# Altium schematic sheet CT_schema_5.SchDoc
size 208 x 258 mm
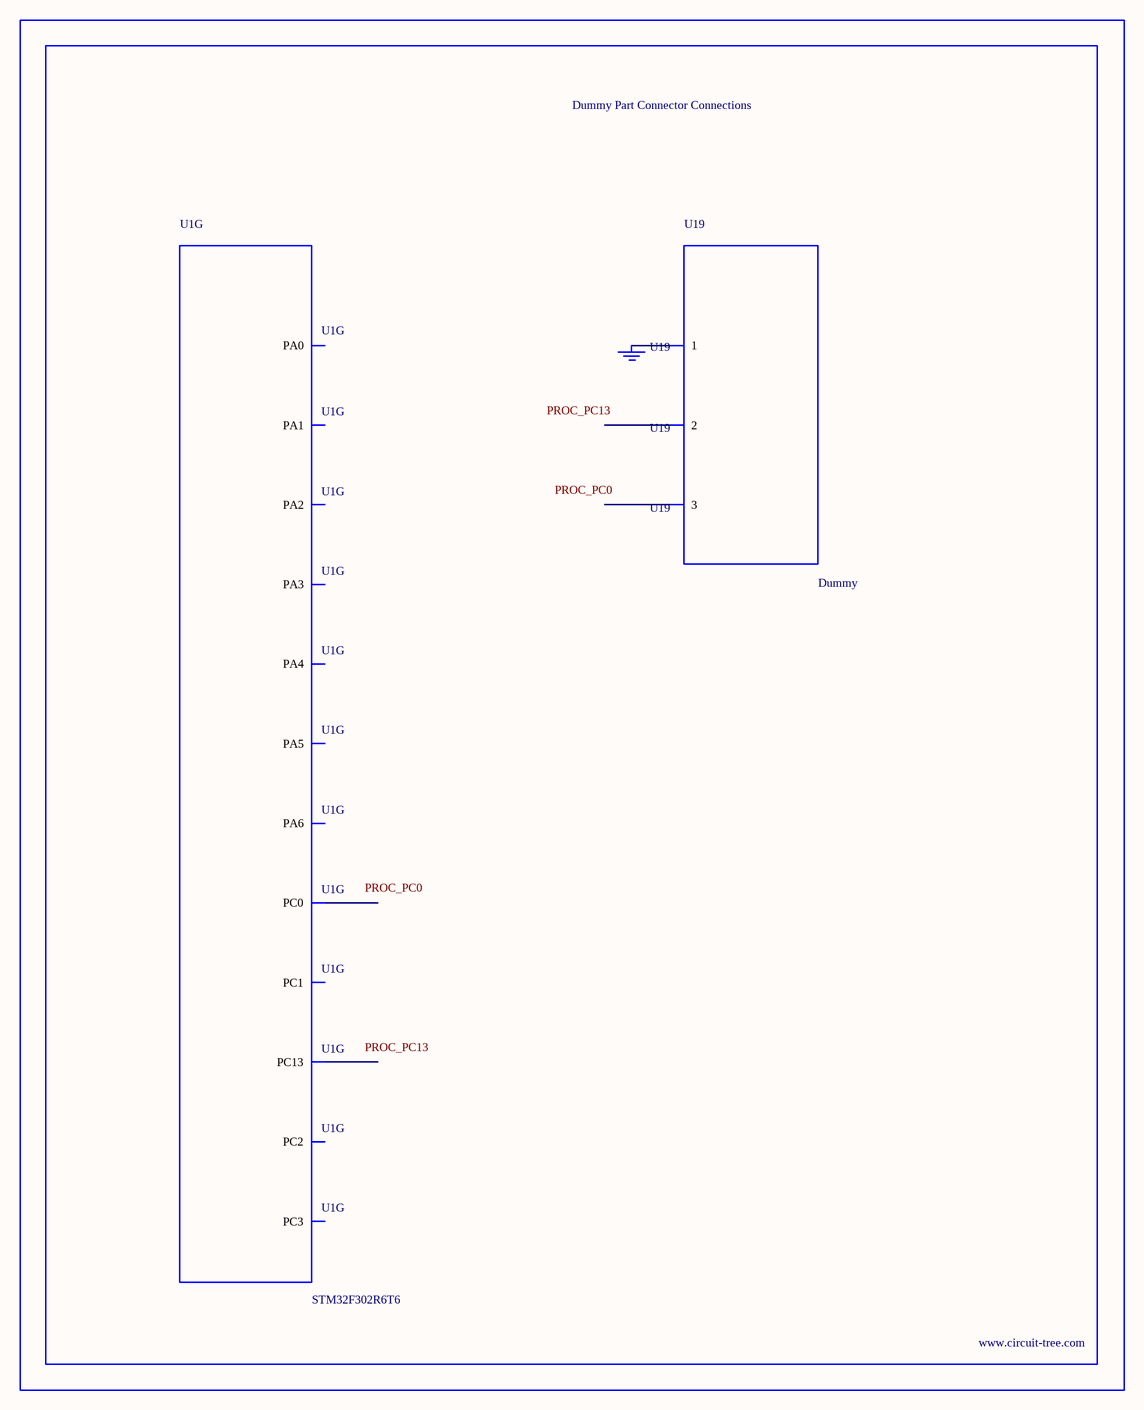
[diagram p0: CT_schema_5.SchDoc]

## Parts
BORDER4  (no value)
GND_INSTANCE_4_0  (no value)
U1  STM32F302R6T6  [LQFP64]  (part G of 7)
U19  Dummy  [DUMMY_PACKAGE_173]

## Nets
NetGND_INSTANCE_4_0_0: GND_INSTANCE_4_0.0(GND) U19.1

Not connected (* = marked no-connect by the designer): U1 2(PC13) 8(PC0) 9(PC1) 10(PC2) 11(PC3) 14(PA0) 15(PA1) 16(PA2) 17(PA3) 20(PA4) 21(PA5) 22(PA6); U19 2 3

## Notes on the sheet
- Labels drawn without touching a wire or pin: PROC_PC0, PROC_PC13

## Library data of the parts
BORDER4 = BORDER_PAGE4
GND_INSTANCE_4_0 = GND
